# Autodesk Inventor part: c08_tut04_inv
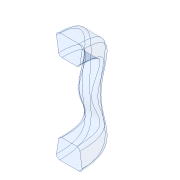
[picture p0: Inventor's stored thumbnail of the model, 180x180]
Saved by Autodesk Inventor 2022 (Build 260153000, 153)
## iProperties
Created: 2015-03
Part Number: c08_tut04_inv
Material: Generic
Document SubType Name: Modeling
Designer: Sandeep
Density: 1 g/cm^3
Appearance: Blue - Glazing
Mass: 996.637 g
Surface Area: 881.078 cm^2
Volume: 996.637 cm^3
Author: Sandeep
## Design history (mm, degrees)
sketch "Sketch1"
  geometry: L1 (-20, 50.541)-(20, 50.541); L2 (30, 60.541)-(30, 70.541); L3 (-30, 60.541)-(-30, 70.541); L4 (0, -9.695)-(0, 120.745); L5 (0, 82)-(-105.666, 82); A1 r 45 centre (0, 37) between (30, 70.541) and (-30, 70.541); A2 r 10 centre (-20, 60.541) between (-30, 60.541) and (-20, 50.541); A3 r 10 centre (20, 60.541) between (20, 50.541) and (30, 60.541); 2 further points
  constraints: 10 end point, 7 point on circle, 5 point on line, 4 tangent, 3 centre point, 2 horizontal, 2 vertical, 1 perpendicular, 1 other
  dimensions: "d0" = 60 distance between parallel lines of L2 L3; "d2" = 20 distance of point (30, 50.541) L2.end; "d3" = 45 radius of A1; "d4" = 10 radius of A2; "d5" = 10 radius of A3; "d22" = 82 distance from line of point (0, 0) L5
sketch "Sketch2"
  geometry: L1 (30.844, 175)-(-30.844, 175); L2 (-40.728, 163.479)-(-33.805, 118.479); L3 (-23.921, 110)-(23.921, 110); L4 (33.805, 118.479)-(40.728, 163.479); L5 (0, 0)-(0, 325.346); A1 r 10 centre (30.844, 165) between (40.728, 163.479) and (30.844, 175); A2 r 10 centre (-30.844, 165) between (-30.844, 175) and (-40.728, 163.479); A3 r 10 centre (-23.921, 120) between (-33.805, 118.479) and (-23.921, 110); A4 r 10 centre (23.921, 120) between (23.921, 110) and (33.805, 118.479); 4 further points
  constraints: 10 end point, 8 point on circle, 8 point on line, 8 tangent, 4 centre point, 3 equal radius, 1 horizontal, 1 parallel, 1 vertical, 1 other
  dimensions: "d6" = 65 distance of point (-32.5, 110) point (32.5, 110); "d7" = 65 distance between parallel lines of L1 L3; "d8" = 85 distance of point (42.5, 175) point (-42.5, 175); "d9" = 175 distance from line of L5.start L1; "d10" = 10 radius of A1
loft "Loft2" sketch "Sketch1", "Sketch2" dims "d23" = 50, "d24" = 90 deg, "d25" = 0, "d26" = 90 deg, "d27" = 50, "d28" = 90 deg
body "Solid2"
sketch "Sketch3"
  geometry: L1 (23.921, -110)-(-23.921, -110); L2 (-33.805, -118.479)-(-40.728, -163.479); L3 (-30.844, -175)-(30.844, -175); L4 (40.728, -163.479)-(33.805, -118.479); L5 (0, 0)-(0, -235.653); A1 r 10 centre (-30.844, -165) between (-40.728, -163.479) and (-30.844, -175); A2 r 10 centre (30.844, -165) between (30.844, -175) and (40.728, -163.479); A3 r 10 centre (23.921, -120) between (33.805, -118.479) and (23.921, -110); A4 r 10 centre (-23.921, -120) between (-23.921, -110) and (-33.805, -118.479); 4 further points
  constraints: 10 end point, 8 point on circle, 8 point on line, 8 tangent, 4 centre point, 3 equal radius, 1 horizontal, 1 parallel, 1 vertical, 1 other
  dimensions: "d11" = 65 distance of point (32.5, -110) point (-32.5, -110); "d12" = 85 distance of point (-42.5, -175) point (42.5, -175); "d13" = 65 distance between parallel lines of L1 L3; "d14" = 175 distance from line of L5.start L3; "d15" = 10 radius of A1
